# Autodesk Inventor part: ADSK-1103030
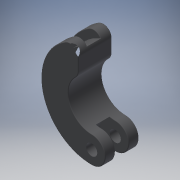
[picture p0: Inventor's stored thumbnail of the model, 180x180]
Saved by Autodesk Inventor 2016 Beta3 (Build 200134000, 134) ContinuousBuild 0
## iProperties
Shininess: 41.0
Length Units: 11272
Angle Units: 11279
Time Units: 11290
Mass Units: 11286
Length Display Precision: 4
Angle Display Precision: 2
Compacted: True
Created: 2000-08
Part Number: ADSK-1103030
Document SubType Name: Modeling
Description: CLUTCH SHOE
Mass: 2.36913 g
Surface Area: 6.11189 cm^2
Volume: 0.525306 cm^3
Density: 4.51 g/cm^3
Material: Titanium
Appearance: Black
Density: 0.0
Volumn: 0.0
Area: 0.0
PropertySet Name: Model Information
Control State: 0
Master: False
Checked Out: False
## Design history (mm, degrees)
node "Extrusion1" dims "d5" = 6.35, "d6" = 0
  sketch "Sketch3"
    geometry: L1 (0, -6.985)-(0, 6.985); L2 (-2.54, 3.648)-(-2.54, 9.18); C1 r 1.048 at (0, -6.985); A1 r 2.54 centre (0, -6.985) between (0, -9.525) and (0, -4.445); A2 r 9.525 centre (0, 0) between (-2.54, 9.18) and (0, -9.525); A3 r 4.445 centre (0, 0) between (-2.54, 3.648) and (0, -4.445); 3 further points
    constraints: 6 point on circle, 5 coincident, 4 centre point, 4 end point, 1 midpoint, 1 parallel, 1 point on line, 1 tangent, 1 vertical
    dimensions: "d0" = 2.0955 diameter of C1; "d4" = 9.525 radius of A2; "d18" = 8.89 diameter of A3; "d19" = 2.54 distance between parallel lines of L1 L2; "d20" = 2.54 radius of A1 (derived)
node "Fillet1" dims "d7" = 1.5875
node "Fillet2" dims "d10" = 1.5875
workplane "Work Plane1"
node "Extrusion2" dims "d12" = 2.54, "d13" = 0
  sketch "Sketch4"
    geometry: C1 r 2.857 at (0, -6.985); 3 further points
    constraints: 1 centre point, 1 coincident, 1 other
    dimensions: "d11" = 5.715 diameter of C1
node "Extrusion3" dims "d14" = 0, "d15" = 0
  sketch "Sketch5"
    geometry: L1 (0, 0)-(1.309, 0) reference; C1 r 1.048 at (0, -6.985) reference; C2 r 8.033 at (0, 0); A1 r 9.525 centre (0, 0) between (0, -9.525) and (1.524, -9.402) reference; 3 further points
    constraints: 2 coincident, 1 centre point, 1 tangent, 5 other
node "Fillet3" dims "d16" = 0.381
node "Fillet4" dims "d17" = 0.127
workaxis "Work Axis1"
body "Solid1"
other parameters: "d1" = 5.08
